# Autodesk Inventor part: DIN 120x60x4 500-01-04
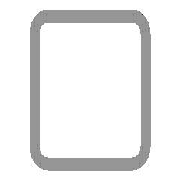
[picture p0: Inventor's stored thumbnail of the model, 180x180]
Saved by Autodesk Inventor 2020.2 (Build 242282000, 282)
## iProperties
Manager: www.cadconsulting.pl
Company: Fabian Stasiak CAD Consulting
Created: 2015-02
Part Number: DIN 120x60x4 500-01-04
Material: Stal
Description: Rurki stalowe o przekroju kwadratowym formowane na gorąco
Document SubType Name: Modellieren
Standard: DIN
Designer: F.Stasiak
Standards Organization: DIN
Language: pl-PL
Size Designation: 120x120x4.5
Categories: <MemberInstance><Categories><Category DisplayName="Kształtowniki konstrukcyjne" InternalName="089c4875-fa83-4c05-b084-43b9cc11f5ed" Mnemonic="GRDR"><CategoryPar
Stock Number: 120x120x4.5
Density: 7.85 g/cm^3
Appearance: Płyta
IsCustomPart: 1
G_L: 970,000 mm
G_W: 120,000 mm
G_H: 120,000 mm
+2FD35156-07EB-433B-8BAA-9E0404799C17+CUTDETAIL1: Wytnij
+0DF8B167-686C-451D-BA79-14E046739711+CUTDETAIL2: Wytnij
_CCFamilyMember: 200
_CCFamilyDisplayName: DIN 59410 (Kwadrat) - Rurki stalowe o przekroju kwadratowym formowane na gorąco — Standard DIN 59410 (Kwadrat) został wycofany i zastąpiony przez standard DIN E
_FrameMemberDoc: Frame Member File
_Version: 15.0.0
_GetPNFromCC: 1
Author: F.Stasiak
Subject: Zbiór ćwiczeń. Autodesk Inventor 2020. Kurs podstawowy
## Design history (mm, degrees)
node "Płaszczyzna początkowa"
node "Płaszczyzna końcowa"
sketch "Szkic"
  geometry: L1 (-51, 60)-(51, 60); L2 (60, 51)-(60, -51); L3 (51, -60)-(-51, -60); L4 (-60, -51)-(-60, 51); L5 (-86.61, 0)-(86.61, 0) reference; L6 (0, -86.61)-(0, 86.61) reference; L7 (-51, 55.5)-(51, 55.5); L8 (55.5, 51)-(55.5, -51); L9 (51, -55.5)-(-51, -55.5); L10 (-55.5, -51)-(-55.5, 51); A1 r 9 centre (-51, 51) between (-51, 60) and (-60, 51); A2 r 9 centre (51, 51) between (60, 51) and (51, 60); A3 r 9 centre (51, -51) between (51, -60) and (60, -51); A4 r 9 centre (-51, -51) between (-60, -51) and (-51, -60); A5 r 4.5 centre (-51, 51) between (-51, 55.5) and (-55.5, 51); A6 r 4.5 centre (51, 51) between (55.5, 51) and (51, 55.5); A7 r 4.5 centre (51, -51) between (51, -55.5) and (55.5, -51); A8 r 4.5 centre (-51, -51) between (-55.5, -51) and (-51, -55.5); 3 further points
  constraints: 16 end point, 16 point on circle, 8 centre point, 8 tangent, 6 point on line, 4 parallel, 3 equal radius, 3 perpendicular, 1 horizontal, 7 other
  dimensions: "b" = 120 distance of point (-60, 60) point (60, 60); "msp_r" = 9 radius of A1 (= 2 x ParT); "d8" = 60 distance between parallel lines of L4 L6 (= d9); "d9" = 60 distance between parallel lines of L3 L5 (= 0.5 x b); "d10" = 4.5 distance between parallel lines of L3 L9 (= ParT)
extrude "Bryła" new body sketch "Szkic" taper "d4" = 0 deg; stored distance "NLG" = 10
node "Driven Length"
  sketch "Sketch2"
    geometry: L1 (0, 0)-(10, 0) reference
    constraints: 2 end point, 1 horizontal
  workplane "Work Plane3"
  sketch "Sketch3"
    geometry: L1 (-2, 60)-(12, 60) reference; L2 (-2, 1030)-(12, 1030) reference
    dimensions: "d14" = 970 distance between parallel lines of L1 L2 (derived)
node "Płaszczyzna konstrukcyjna4"
feature "Podział1"
node "Płaszczyzna konstrukcyjna5"
feature "Podział2"
body "Solid1"
other parameters: "ParT" = 4.5, "G_L" = 970 (= d14) [user parameter], "d13" = 90 deg
